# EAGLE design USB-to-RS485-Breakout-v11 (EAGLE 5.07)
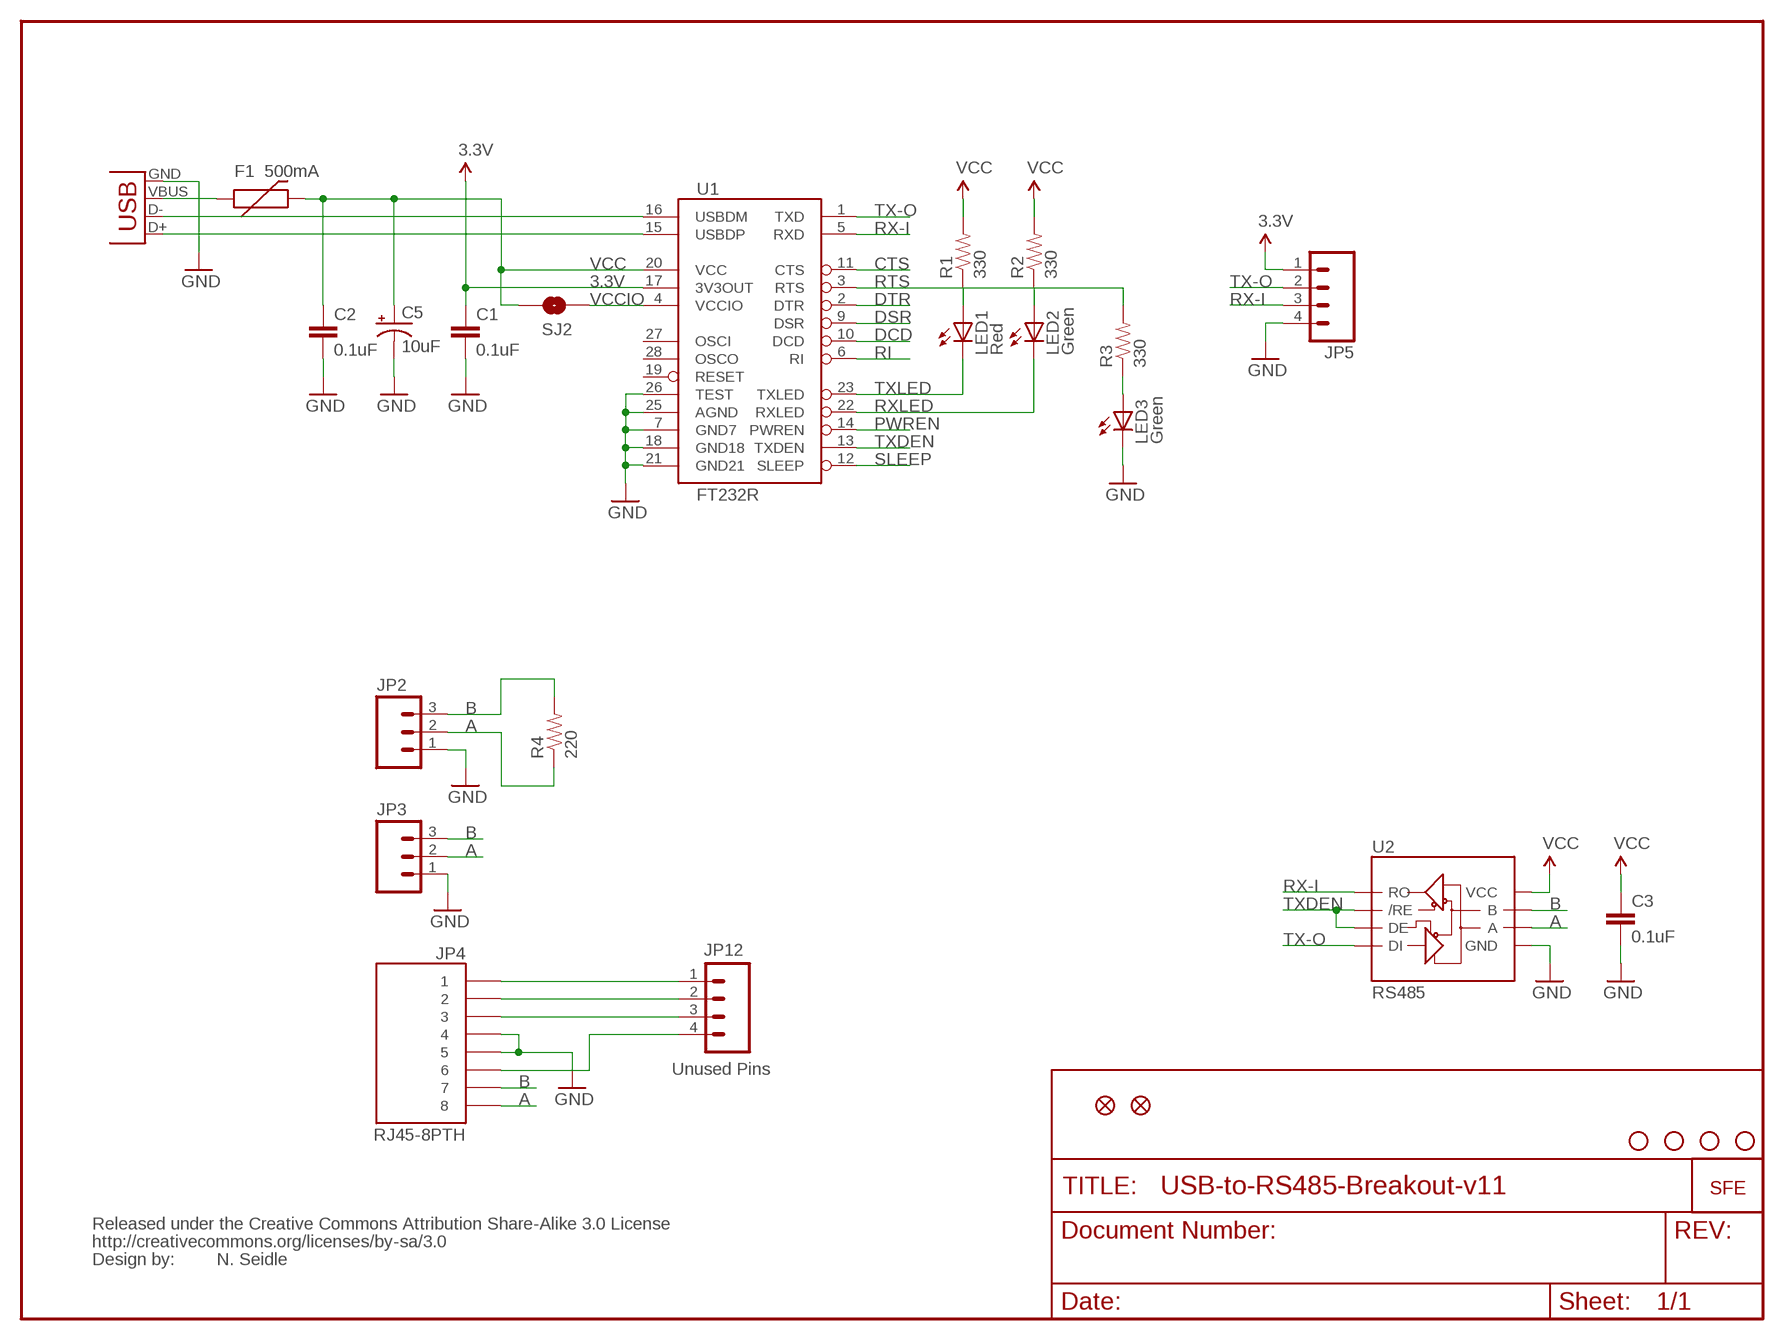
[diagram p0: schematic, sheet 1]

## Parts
C1  0.1uF  CAP0402-CAP  [0402-CAP]
C2  0.1uF  CAP0402-CAP  [0402-CAP]
C3  0.1uF  CAP0402-CAP  [0402-CAP]
C5  10uF  CAP_POL1206  [EIA3216]
F1  500mA  PTCSMD  [PTC-1206]
JP1  STAND-OFF  [STAND-OFF]
JP2  M03SCREW  [SCREWTERMINAL-3.5MM-3]
JP3  M03PTH  [1X03]
JP4  RJ45-8PTH  [RJ45-8]
JP5  M04PTH  [1X04]
JP6  STAND-OFF  [STAND-OFF]
JP7  STAND-OFF  [STAND-OFF]
JP8  STAND-OFF  [STAND-OFF]
JP9  FIDUCIAL1X2  [FIDUCIAL-1X2]
JP10  FIDUCIAL1X2  [FIDUCIAL-1X2]
JP12  Unused Pins  M04PTH  [1X04]
LED1  Red  LED0603  [LED-0603]
LED2  Green  LED0603  [LED-0603]
LED3  Green  LED0603  [LED-0603]
R1  330  RESISTOR0402-RES  [0402-RES]
R2  330  RESISTOR0402-RES  [0402-RES]
R3  330  RESISTOR0402-RES  [0402-RES]
R4  220  RESISTOR0402-RES  [0402-RES]
SJ2  SOLDERJUMPERNC2  [SJ_2S-NOTRACE]
U1  FT232R  FT232RLSSOP  [SSOP28DB]
U2  RS485  RS485SOIC  [SO08]
U$1  CREATIVE_COMMONS  [CREATIVE_COMMONS]
U$2  LOGO-SFENEW  [SFE-NEW-WEBLOGO]
X2  USBSMD  [USB-MINIB]

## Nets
3.3V [power]: C1.1 JP5.1 U1.17(3V3OUT)
A: JP2.2 JP3.2 JP4.8 R4.1 U2.6(A)
B: JP2.3 JP3.3 JP4.7 R4.2 U2.7(B)
CTS: U1.11(CTS)
DCD: U1.10(DCD)
DSR: U1.9(DSR)
DTR: U1.2(DTR)
GND [power]: C1.2 C2.2 C3.2 C5.C(-) JP2.1 JP3.1 JP4.4 JP4.5 JP5.4 LED3.C U1.7(GND7) U1.18(GND18) U1.21(GND21) U1.25(AGND) U1.26(TEST) U2.5(GND) X2.GND
N$1: LED1.A R1.1
N$2: LED2.A R2.1
N$3: F1.1 X2.VBUS
N$4: LED3.A R3.1
N$5: JP4.1 JP12.1
N$6: JP4.2 JP12.2
N$7: JP4.3 JP12.3
N$8: JP4.6 JP12.4
PWREN: U1.14(PWREN)
RI: U1.6(RI)
RTS: R3.2 U1.3(RTS)
RX-I: JP5.3 U1.5(RXD) U2.1(RO)
RXLED: LED2.C U1.22(RXLED)
SLEEP: U1.12(SLEEP)
TX-O: JP5.2 U1.1(TXD) U2.4(DI)
TXDEN: U1.13(TXDEN) U2.2(/RE) U2.3(DE)
TXLED: LED1.C U1.23(TXLED)
USB_D+: U1.15(USBDP) X2.D+
USB_D-: U1.16(USBDM) X2.D-
VCC [power]: C2.1 C3.1 C5.A(+) F1.2 R1.2 R2.2 SJ2.2 U1.20(VCC) U2.8(VCC)
VCCIO: SJ2.1 U1.4(VCCIO)
Unconnected: U1.19(RESET) U1.27(OSCI) U1.28(OSCO)

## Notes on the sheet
- N. Seidle

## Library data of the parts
C1-C3 = SparkFun:CAP: Capacitor
C5 = SparkFun:CAP_POL: Capacitor Polarized
F1 = SparkFun:PTC: Resettable Fuse PTC
JP1 JP6-JP8 = SparkFun:STAND-OFF: Stand Off
JP2 JP3 = SparkFun:M03: Header 3 Standard 3-pin 0.1" header. Use with straight break away headers (SKU : PRT-00116), right angle break away headers (PRT-00553), swiss pins (PRT-00743), machine pins (PRT-00117), and female headers (PRT-00115). Molex polarized connector foot print use with SKU : PRT-08232 with associated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
JP4 = SparkFun:RJ45-8: RJ45 Jack Simple RJ45, 8-pin connection - connector for common Cat5, Cat5e, and Cat6 Ethernet cables. Footprint not yet proven in production. Connector sku is PRT-00643; Breakout PCB sku is BOB-00716.
JP5 JP12 = SparkFun:M04: Header 4 Standard 4-pin 0.1" header. Use with straight break away headers (SKU : PRT-00116), right angle break away headers (PRT-00553), swiss pins (PRT-00743), machine pins (PRT-00117), and female headers (PRT-00115). Molex polarized connector foot print use with SKU : PRT-08231 with associated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
JP9 JP10 = SparkFun:FIDUCIAL: Fiducial Alignment Points
LED1-LED3 = SparkFun:LED: LEDs
R1-R4 = SparkFun:RESISTOR: Resistor
SJ2 = SparkFun:SOLDERJUMPER: Solder Jumper
U1 = SparkFun:FT232RL: USB UART FT232RL 4th Generation USB UART (USB <-> Serial) Controller. Spark Fun Electronics SKU : COM-00650
U2 = SparkFun:RS485
U$1 = SparkFun:CREATIVE_COMMONS
U$2 = SparkFun:LOGO-SFE: Spark Fun Electronics PCB Logo
X2 = SparkFun:USB: USB Connectors USB-B-PTH is fully proven SKU : PRT-00139 USB-miniB is fully proven SKU : PRT-00587 USB-A-PCB is untested. USB-A-H is throughly reviewed, but untested. Spark Fun Electronics SKU : PRT-00437 USB-B-SMT is throughly reviewed, but untested. Needs silkscreen touching up. USB-A-S has not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

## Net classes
0 default: width 0.203 mm
1 power: width 0.254 mm

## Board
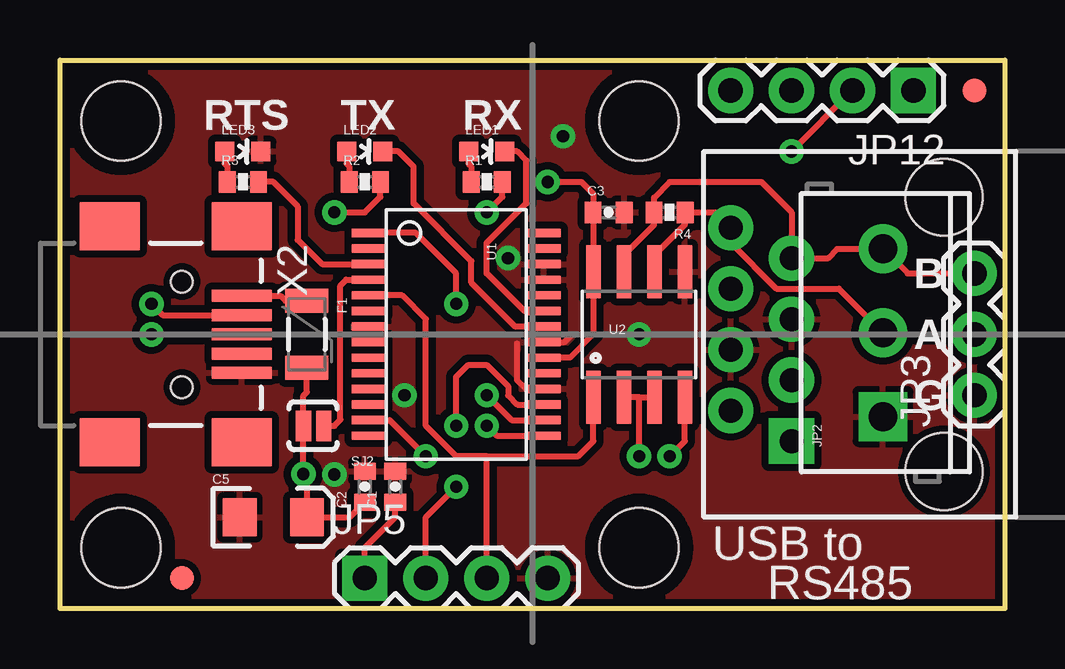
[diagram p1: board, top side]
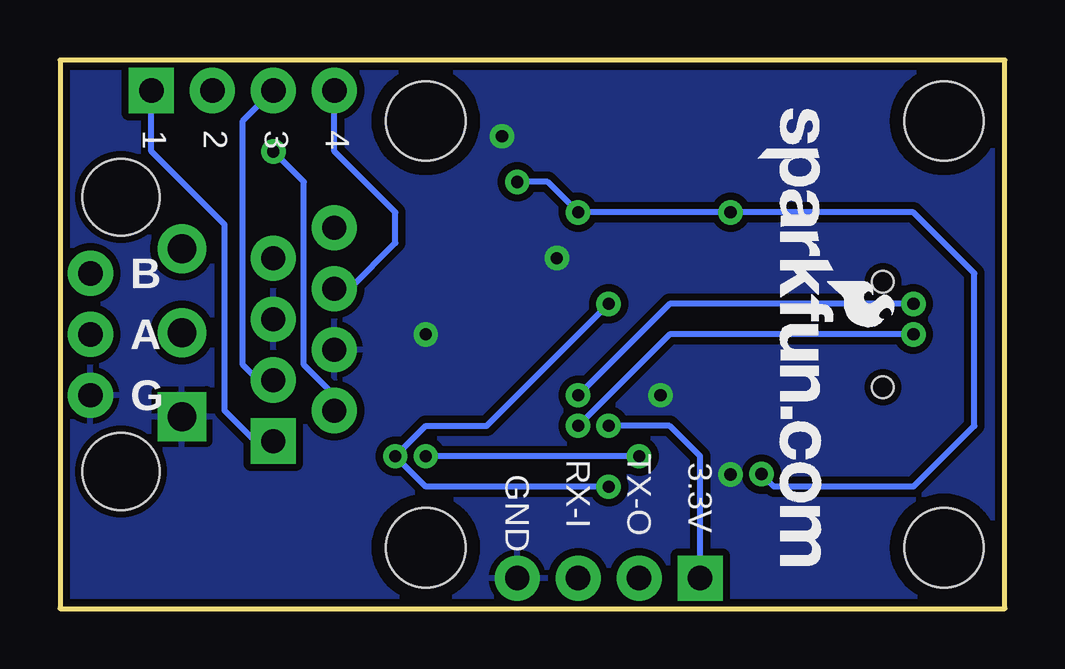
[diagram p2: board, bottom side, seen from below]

Size 39.37 x 22.86 mm. Coordinates in mm from the lower left corner, seen from the top.
Outline: 39.37,0 0,0 0,22.86 39.37,22.86 39.37,0
Copper layers (1*16): Top 0.035mm / dielectric 1.5mm / Bottom 0.035mm
Design rules "SparkFun": minimum track width 8mil, minimum drill 20mil, track to track 8mil, track to pad 8mil, pad to pad 8mil, via to via 8mil, smd to smd 8mil, copper to edge 8mil, drill to drill 8mil, minimum pad ring 12mil, minimum via ring 10mil, stop-mask expansion 4mil, vias tented up to drill 20mil, thermal gap 10mil

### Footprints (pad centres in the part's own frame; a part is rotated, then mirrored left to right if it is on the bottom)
0402-CAP = smd 0.7 x 0.9: 1 -0.65,0; 2 0.65,0
EIA3216 = smd 1.4 x 1.6: A 1.4,0; C -1.4,0
PTC-1206 = smd 1 x 1.8: 1 -1.4,0; 2 1.4,0
STAND-OFF = hole 3.302: 0,0
SCREWTERMINAL-3.5MM-3 = drill 1.2 pad 2.032 square: 1 0,0 | drill 1.2 pad 2.032 round: 2 3.5,0; 3 7,0
1X03 = drill 1.016 pad 1.88 round: 1 0,0; 2 2.54,0; 3 5.08,0
RJ45-8 = drill 1 pad 1.88 square: 1 -4.445,6.35 | drill 1 pad 1.88 round: 2 -3.175,8.89; 3 -1.905,6.35; 4 -0.635,8.89; 5 0.635,6.35; 6 1.905,8.89; 7 3.175,6.35; 8 4.445,8.89 | hole 3.2: -5.715,0; 5.715,0
1X04 = drill 1.016 pad 1.88 square: 1 0,0 | drill 1.016 pad 1.88 round: 2 2.54,0; 3 5.08,0; 4 7.62,0
FIDUCIAL-1X2 = smd 1 x 1: 1 0,0
LED-0603 = smd 0.8 x 0.8: A 0,-0.75; C 0,0.75
0402-RES = smd 0.7 x 0.9: 1 -0.65,0; 2 0.65,0
SJ_2S-NOTRACE = smd 0.635 x 1.27: 1 -0.45,0; 2 0.4,0
SSOP28DB = smd 0.348 x 1.397: 1 -4.225,-3.656; 2 -3.575,-3.656; 3 -2.925,-3.656; 4 -2.275,-3.656; 5 -1.625,-3.656; 6 -0.975,-3.656; 7 -0.325,-3.656; 8 0.325,-3.656; 9 0.975,-3.656; 10 1.625,-3.656; 11 2.275,-3.656; 12 2.925,-3.656; 13 3.575,-3.656; 14 4.225,-3.656; 15 4.225,3.656; 16 3.575,3.656; 17 2.925,3.656; 18 2.275,3.656; 19 1.625,3.656; 20 0.975,3.656; 21 0.325,3.656; 22 -0.325,3.656; 23 -0.975,3.656; 24 -1.625,3.656; 25 -2.275,3.656; 26 -2.925,3.656; 27 -3.575,3.656; 28 -4.225,3.656
SO08 = smd 0.61 x 2.21: 1 -1.905,-2.616; 2 -0.635,-2.616; 3 0.635,-2.616; 4 1.905,-2.616; 5 1.905,2.616; 6 0.635,2.616; 7 -0.635,2.616; 8 -1.905,2.616
USB-MINIB = smd 2.5 x 0.5: D+ 2.5,0; D- 2.5,0.8; GND 2.5,-1.6; ID 2.5,-0.8; VBUS 2.5,1.6 | smd 2.5 x 2: GND@1 -3,-4.5; GND@2 -3,4.5; GND@3 2.5,4.5; GND@4 2.5,-4.5 | hole 0.9: 0,2.2; 0,-2.2

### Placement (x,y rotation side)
C1  13.97,5.08 90 top
C2  12.7,5.08 90 top
C3  22.86,16.51 0 top
C5  8.89,3.81 0 top
F1  10.29,11.43 270 top
JP1  2.54,20.32 0 top
JP2  34.29,8 90 top
JP3  38.1,8.89 90 top
JP4  36.83,11.43 90 top
JP5  12.7,1.27 0 top
JP6  2.54,2.54 0 top
JP7  24.13,20.32 0 top
JP8  24.13,2.54 0 top
JP9  5.08,1.27 0 top
JP10  38.1,21.59 0 top
JP12  35.56,21.59 180 top
LED1  17.78,19.05 270 top
LED2  12.7,19.05 270 top
LED3  7.62,19.05 270 top
R1  17.78,17.78 0 top
R2  12.7,17.78 0 top
R3  7.62,17.78 0 top
R4  25.4,16.51 180 top
SJ2  10.54,7.62 180 top
U1  16.51,11.43 270 top
U2  24.13,11.43 0 top
U$1  not placed on the board
U$2  10.29,20.83 270 bottom
X2  5.08,11.43 0 top

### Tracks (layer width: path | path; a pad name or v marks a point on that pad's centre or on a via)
3.3V  (via drill 0.51)
  Top 0.254: C1.1 13.97,3.81 12.7,2.54 JP5.1 | v16.51,7.62 16.51,9.65 17.02,10.16 17.78,10.16 18.67,9.27 18.67,8.89 19.05,8.51 U1.17
  Bottom 0.254: v16.51,7.62 13.97,7.62 12.7,6.35 JP5.1
A
  Top 0.254: JP3.2 34.36,11.43 JP2.2 32.46,13.34 29.84,13.34 27.94,15.24 JP4.8 27.3,16.51 R4.1 26.05,16.02 24.77,14.73 U2.6
B
  Top 0.254: JP3.3 35.32,13.97 JP2.3 34.27,14.99 32.38,14.99 32,14.61 JP4.7 30.48,16.51 29.21,17.78 25.4,17.78 24.75,17.13 R4.2 24.75,15.99 23.5,14.73 U2.7
GND  (via drill 0.51)
  Top 0.254: U1.21 21.01,11.11 21.34,11.43 | U1.18 19.42,9.15 19.05,9.53 19.05,11.05
  other vias: 18.67,14.61 11.43,5.59 24.13,11.43 20.95,19.68 14.35,8.89
  pour Bottom (isolate 0.305): 39.37,22.86 39.37,0 0,0 0,22.86
  pour Top (isolate 0.305): 39.37,22.86 39.37,0 0,0 0,22.86
N$1
  Top 0.254: R1.1 17.13,18.43 17.02,18.54 17.02,19.04 LED1.A
N$2
  Top 0.254: R2.1 12.05,18.43 11.94,18.54 11.94,19.04 LED2.A
N$3
  Top 0.254: X2.VBUS 9.2,13.03 9.4,12.83 10.54,12.83 F1.1
N$4
  Top 0.254: R3.1 6.97,18.43 6.86,18.54 6.86,19.04 LED3.A
N$5
  Bottom 0.254: JP4.1 31.24,6.99 32.51,8.26 32.51,16 35.56,19.05 JP12.1
N$6  (via drill 0.51)
  Top 0.254: v30.48,19.05 JP12.2
  Bottom 0.254: JP4.2 27.94,8.89 29.21,10.16 29.21,17.78 v30.48,19.05
N$7
  Bottom 0.254: JP4.3 31.11,9.53 31.75,10.16 31.75,20.32 JP12.3
N$8
  Bottom 0.254: JP4.6 27.3,13.34 25.4,15.24 25.4,16.51 27.94,19.05 JP12.4
RTS
  Top 0.254: U1.3 10.92,14.36 9.91,15.37 9.91,16.76 8.89,17.78 R3.2
RX-I
  Top 0.254: U2.1 22.23,6.99 21.59,6.35 17.78,6.35 | 17.78,6.35 16.51,6.35 15.24,7.62 15.24,12.06 14.25,13.05 U1.5 | JP5.3 17.78,6.35
RXLED
  Top 0.254: U1.22 18.98,11.76 17.14,13.59 17.14,14.48 14.73,16.89 14.73,18.41 14.1,19.05 LED2.C
TX-O  (via drill 0.51)
  Top 0.254: JP5.2 15.24,3.81 v16.51,5.08 | v16.51,12.7 16.51,13.97 14.82,15.65 U1.1 | U2.4 26.04,6.99 v25.4,6.35
  Bottom 0.254: v16.51,12.7 21.59,7.62 24.13,7.62 v25.4,6.35 24.13,5.08 v16.51,5.08
TXDEN  (via drill 0.51)
  Top 0.254: 24.13,8.81 U2.2 | 24.13,8.81 U2.3 | U1.13 13.73,7.86 v15.24,6.35 | v24.13,6.35 24.13,8.81
  Bottom 0.254: v15.24,6.35 v24.13,6.35
TXLED
  Top 0.254: U1.23 19.34,12.4 17.78,13.97 17.78,15.24 19.43,16.89 19.43,18.67 19.05,19.05 LED1.C
USB_D+  (via drill 0.51)
  Top 0.254: v3.81,11.43 X2.D+ | U1.15 18.2,7.21 v17.78,7.62
  Bottom 0.254: v3.81,11.43 13.97,11.43 v17.78,7.62
USB_D-  (via drill 0.51)
  Top 0.254: U1.16 18.82,7.86 v17.78,8.89 | X2.D- 4.28,12.23 v3.81,12.7
  Bottom 0.254: v17.78,8.89 13.97,12.7 v3.81,12.7
VCC  (via drill 0.51)
  Top 0.254: U1.20 21.25,10.46 22.23,11.43 U2.8 22.23,16.5 C3.1 22.21,17.29 21.72,17.78 v20.32,17.78 | R2.2 13.35,17.16 12.7,16.51 v11.43,16.51 | R1.2 18.43,17.16 v17.78,16.51 | C2.1 12.08,3.81 C5.A 10.29,5.46 v10.14,5.61 SJ2.2 10.14,8.87 10.29,9.02 F1.2
  Bottom 0.254: v10.14,5.61 9.61,5.08 3.81,5.08 1.27,7.62 1.27,13.97 3.81,16.51 v11.43,16.51 v17.78,16.51 19.05,17.78 v20.32,17.78
VCCIO
  Top 0.254: SJ2.1 11.43,7.62 11.68,7.87 11.68,13.46 11.93,13.71 U1.4

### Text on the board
tPlace: RTS | TX | RX | B | A | G | USB to | RS485 | N. Seidle
bPlace: 4 | 3 | 2 | 1 | B | A | G | 3.3V | TX-O | RX-I | GND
